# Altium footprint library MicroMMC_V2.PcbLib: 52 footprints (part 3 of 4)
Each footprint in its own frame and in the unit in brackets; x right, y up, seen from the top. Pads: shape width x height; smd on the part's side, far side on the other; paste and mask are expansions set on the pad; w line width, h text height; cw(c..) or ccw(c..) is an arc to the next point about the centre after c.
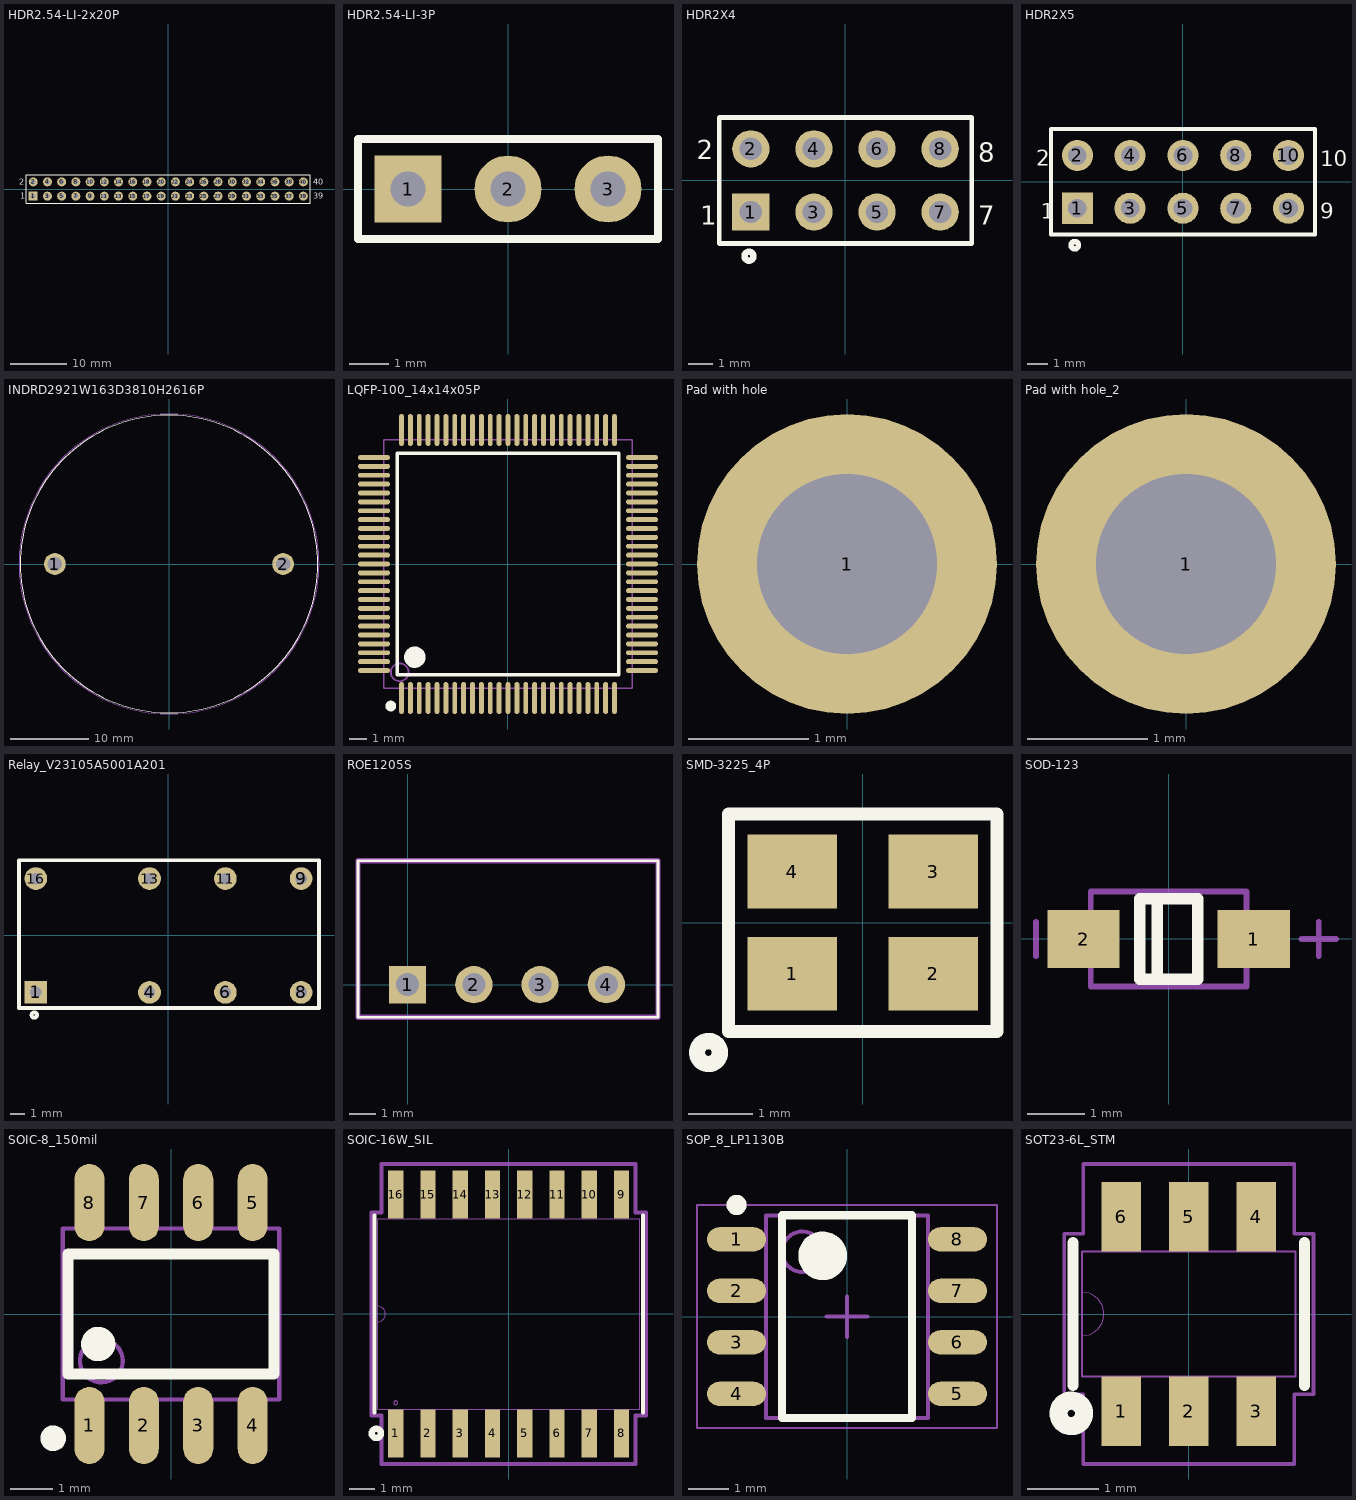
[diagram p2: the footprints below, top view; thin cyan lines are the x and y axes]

## HDR2.54-LI-2x20P [mm] "双排排针，20x2脚"
pads (40):
  rect 1.6x1.6 hole 0.9: 1(-24.13,-1.27)
  round 1.6 hole 0.9: 2(-24.13,1.27) 3(-21.59,-1.27) 4(-21.59,1.27) 5(-19.05,-1.27) 6(-19.05,1.27) 7(-16.51,-1.27) 8(-16.51,1.27) 9(-13.97,-1.27) 10(-13.97,1.27) 11(-11.43,-1.27) 12(-11.43,1.27) 13(-8.89,-1.27) 14(-8.89,1.27) 15(-6.35,-1.27) 16(-6.35,1.27) 17(-3.81,-1.27) 18(-3.81,1.27) 19(-1.27,-1.27) 20(-1.27,1.27) 21(1.27,-1.27) 22(1.27,1.27) 23(3.81,-1.27) 24(3.81,1.27) 25(6.35,-1.27) 26(6.35,1.27) 27(8.89,-1.27) 28(8.89,1.27) 29(11.43,-1.27) 30(11.43,1.27) 31(13.97,-1.27) 32(13.97,1.27) 33(16.51,-1.27) 34(16.51,1.27) 35(19.05,-1.27) 36(19.05,1.27) 37(21.59,-1.27) 38(21.59,1.27) 39(24.13,-1.27) 40(24.13,1.27)
Top Overlay:
  lines w0.2: -25.4,-2.54 25.4,-2.54 25.4,2.54 -25.4,2.54 -25.4,-2.54
  text "1" at -26.416,-1.778 h1.02
  text "2" at -26.67,0.762 h1.02
  text "40" at 25.908,0.762 h1.02
  text "39" at 25.908,-1.778 h1.02
3D body "HDR2.54-1x2P.STEP": height 8.5, standoff -3, extent 17.78,-2.54 20.32,2.54
3D body "HDR2.54-1x2P.STEP": height 8.5, standoff -3, extent 20.32,-2.54 22.86,2.54
3D body "HDR2.54-1x2P.STEP": height 8.5, standoff -3, extent 12.7,-2.54 15.24,2.54
3D body "HDR2.54-1x2P.STEP": height 8.5, standoff -3, extent 15.24,-2.54 17.78,2.54
3D body "HDR2.54-1x2P.STEP": height 8.5, standoff -3, extent 22.86,-2.54 25.4,2.54
3D body "HDR2.54-1x2P.STEP": height 8.5, standoff -3, extent 5.08,-2.54 7.62,2.54
3D body "HDR2.54-1x2P.STEP": height 8.5, standoff -3, extent 7.62,-2.54 10.16,2.54
3D body "HDR2.54-1x2P.STEP": height 8.5, standoff -3, extent 0,-2.54 2.54,2.54
3D body "HDR2.54-1x2P.STEP": height 8.5, standoff -3, extent 2.54,-2.54 5.08,2.54
3D body "HDR2.54-1x2P.STEP": height 8.5, standoff -3, extent 10.16,-2.54 12.7,2.54
3D body "HDR2.54-1x2P.STEP": height 8.5, standoff -3, extent -7.62,-2.54 -5.08,2.54
3D body "HDR2.54-1x2P.STEP": height 8.5, standoff -3, extent -5.08,-2.54 -2.54,2.54
3D body "HDR2.54-1x2P.STEP": height 8.5, standoff -3, extent -12.7,-2.54 -10.16,2.54
3D body "HDR2.54-1x2P.STEP": height 8.5, standoff -3, extent -10.16,-2.54 -7.62,2.54
3D body "HDR2.54-1x2P.STEP": height 8.5, standoff -3, extent -2.54,-2.54 0,2.54
3D body "HDR2.54-1x2P.STEP": height 8.5, standoff -3, extent -20.32,-2.54 -17.78,2.54
3D body "HDR2.54-1x2P.STEP": height 8.5, standoff -3, extent -17.78,-2.54 -15.24,2.54
3D body "HDR2.54-1x2P.STEP": height 8.5, standoff -3, extent -25.4,-2.54 -22.86,2.54
3D body "HDR2.54-1x2P.STEP": height 8.5, standoff -3, extent -22.86,-2.54 -20.32,2.54
3D body "HDR2.54-1x2P.STEP": height 8.5, standoff -3, extent -15.24,-2.54 -12.7,2.54

## HDR2.54-LI-3P [mm] "排针，3脚"
pads (3):
  rect 1.7x1.7 hole 0.9: 1(-2.54,0)
  round 1.7 hole 0.9: 2(0,0) 3(2.54,0)
Top Overlay:
  lines w0.2: -3.81,-1.27 -3.81,1.27 3.81,1.27 3.81,-1.27 -3.81,-1.27
3D body "HDR2.54-1P.STEP": height 8.5, standoff -3, extent 1.27,-1.27 3.81,1.27
3D body "HDR2.54-1P.STEP": height 8.5, standoff -3, extent -1.27,-1.27 1.27,1.27
3D body "HDR2.54-1P.STEP": height 8.5, standoff -3, extent -3.81,-1.27 -1.27,1.27

## HDR2X4 [mm] "Connector; Header; 4x2 Position"
pads (8):
  rect 1.5x1.5 hole 0.9: 1(-3.81,-1.27)
  round 1.5 hole 0.9: 2(-3.81,1.27) 3(-1.27,-1.27) 4(-1.27,1.27) 5(1.27,-1.27) 6(1.27,1.27) 7(3.81,-1.27) 8(3.81,1.27)
Top Overlay:
  circle w0.254: c-3.884,-3.048 r0.18
  lines w0.2: -5.08,-2.54 5.08,-2.54 5.08,2.54 -5.08,2.54 -5.08,-2.54
  text "2" at -5.975,0.852 h0.76
  text "1" at -5.842,-1.778 h0.76
  text "7" at 5.334,-1.778 h0.76
  text "8" at 5.334,0.762 h0.76

## HDR2X5 [mm] "Connector; Header; 5x2 Position"
pads (10):
  rect 1.5x1.5 hole 0.9: 1(-5.08,-1.27)
  round 1.5 hole 0.9: 2(-5.08,1.27) 3(-2.54,-1.27) 4(-2.54,1.27) 5(0,-1.27) 6(0,1.27) 7(2.54,-1.27) 8(2.54,1.27) 9(5.08,-1.27) 10(5.08,1.27)
Top Overlay:
  circle w0.254: c-5.207,-3.048 r0.18
  lines w0.2: -6.35,-2.54 6.35,-2.54 6.35,2.54 -6.35,2.54 -6.35,-2.54
  text "2" at -7.071,0.787 h0.76
  text "1" at -6.853,-1.77 h0.76
  text "9" at 6.604,-1.778 h0.76
  text "10" at 6.604,0.762 h0.76

## INDRD2921W163D3810H2616P [mm]
pads (2):
  round 2.8 hole 1.85: 1(-14.605,0) 2(14.605,0)
Top Overlay:
  circle w0.127: c0,0 r19.05
Mechanical 15:
  circle w0.127: c0,0 r19.2
3D body "1140-122k-rc.stp": height 26.23, standoff -12.63, extent -19.05,-19.05 19.05,19.05

## LQFP-100_14x14x05P [mm]
pads (100):
  oval 0.28x1.8 smd: 1(-6,-7.55) 2(-5.5,-7.55) 3(-5,-7.55) 4(-4.5,-7.55) 5(-4,-7.55) 6(-3.5,-7.55) 7(-3,-7.55) 8(-2.5,-7.55) 9(-2,-7.55) 10(-1.5,-7.55) 11(-1,-7.55) 12(-0.5,-7.55) 13(0,-7.55) 14(0.5,-7.55) 15(1,-7.55) 16(1.5,-7.55) 17(2,-7.55) 18(2.5,-7.55) 19(3,-7.55) 20(3.5,-7.55) 21(4,-7.55) 22(4.5,-7.55) 23(5,-7.55) 24(5.5,-7.55) 25(6,-7.55) 51(6,7.55) 52(5.5,7.55) 53(5,7.55) 54(4.5,7.55) 55(4,7.55) 56(3.5,7.55) 57(3,7.55) 58(2.5,7.55) 59(2,7.55) 60(1.5,7.55) 61(1,7.55) 62(0.5,7.55) 63(0,7.55) 64(-0.5,7.55) 65(-1,7.55) 66(-1.5,7.55) 67(-2,7.55) 68(-2.5,7.55) 69(-3,7.55) 70(-3.5,7.55) 71(-4,7.55) 72(-4.5,7.55) 73(-5,7.55) 74(-5.5,7.55) 75(-6,7.55)
  oval 1.8x0.28 smd: 26(7.55,-6) 27(7.55,-5.5) 28(7.55,-5) 29(7.55,-4.5) 30(7.55,-4) 31(7.55,-3.5) 32(7.55,-3) 33(7.55,-2.5) 34(7.55,-2) 35(7.55,-1.5) 36(7.55,-1) 37(7.55,-0.5) 38(7.55,0) 39(7.55,0.5) 40(7.55,1) 41(7.55,1.5) 42(7.55,2) 43(7.55,2.5) 44(7.55,3) 45(7.55,3.5) 46(7.55,4) 47(7.55,4.5) 48(7.55,5) 49(7.55,5.5) 50(7.55,6) 76(-7.55,6) 77(-7.55,5.5) 78(-7.55,5) 79(-7.55,4.5) 80(-7.55,4) 81(-7.55,3.5) 82(-7.55,3) 83(-7.55,2.5) 84(-7.55,2) 85(-7.55,1.5) 86(-7.55,1) 87(-7.55,0.5) 88(-7.55,0) 89(-7.55,-0.5) 90(-7.55,-1) 91(-7.55,-1.5) 92(-7.55,-2) 93(-7.55,-2.5) 94(-7.55,-3) 95(-7.55,-3.5) 96(-7.55,-4) 97(-7.55,-4.5) 98(-7.55,-5) 99(-7.55,-5.5) 100(-7.55,-6)
Top Overlay:
  circle w0.6: c-5.25,-5.25 r0.3
  circle w0.3: c-6.604,-8.001 r0.15
  lines w0.2: -6.25,-6.25 6.25,-6.25 6.25,6.25 -6.25,6.25 -6.25,-6.25
Mechanical 13:
  circle w0.1: c-6.1,-6.1 r0.5
  lines w0.1: -7,-7 7,-7 7,7 -7,7 -7,-7
3D body "LQFP-100.STEP": height 1.6, standoff 0, extent -8,-8 8,8

## Pad with hole [mm]
pads (1):
  round 2.5 hole 1.5: 1(0,0)

## Pad with hole_2 [mm]
pads (1):
  round 2.5 hole 1.5: 1(0,0)

## Relay_V23105A5001A201 [mil] "V23105A5001A201"
pads (8):
  rect 60x60 hole 30: 1(-350,-150)
  round 60 hole 30: 4(-50,-150) 6(150,-150) 8(350,-150) 9(350,150) 11(150,150) 13(-50,150) 16(-350,150)
Top Overlay:
  circle w10: c-354.02,-210 r7.07
  lines w10: -394.29,-191.34 397.05,-191.34 397.05,198.43 -394.29,198.43 -394.29,-191.34
3D body "V23105A5001A201_Relay v2.step": height 425.7, standoff -78.24, extent -394.29,-191.34 397.05,198.42

## ROE1205S [mm]
pads (4):
  rect 1.43x1.43 hole 0.88: 1(0,0)
  round 1.43 hole 0.88: 2(2.54,0) 3(5.08,0) 4(7.62,0)
Top Overlay:
  lines w0.1: -1.9,-1.25 9.6,-1.25 9.6,4.75 -1.9,4.75 -1.9,-1.25
Mechanical 13:
  lines w0.2: -1.9,-1.25 9.6,-1.25 9.6,4.75 -1.9,4.75 -1.9,-1.25
3D body "ROE-0512S.stp": height 10.6, standoff -5, extent -1.9,-1.25 9.6,4.75

## SMD-3225_4P [mm]
pads (4):
  rect 1.4x1.15 smd: 1(-1.1,-0.8) 2(1.1,-0.8) 3(1.1,0.8) 4(-1.1,0.8)
Top Overlay:
  circle w0.254: c-2.413,-2.032 r0.18
  lines w0.203: -2.1,-1.7 2.1,-1.7 2.1,1.7 -2.1,1.7 -2.1,-1.7
3D body "User Library-3225-1.STEP": height 0.61, standoff 0, extent -1.6,-1.25 1.6,1.25

## SOD-123 [mm]
pads (2):
  rect 1.25x1 smd: 1(1.475,0) 2(-1.475,0)
Top Overlay:
  lines w0.2: -0.2,-0.7 -0.2,0.7 ; -0.5,-0.7 0.5,-0.7 0.5,0.7 -0.5,0.7 -0.5,-0.7
Mechanical 13:
  lines w0.1: -1.35,-0.825 -1.35,0.825 1.35,0.825 1.35,-0.825 -1.35,-0.825
Mechanical 15:
  lines w0.1: -2.3,-0.3 -2.3,0.3 ; 2.3,0 2.9,0 ; 2.6,-0.3 2.6,0.3
3D body "SOD123.STEP": height 1.35, standoff 0, extent -1.85,-0.775 1.85,0.775

## SOIC-8_150mil [mm]
pads (8):
  oval 0.7x1.8 smd: 1(-1.905,-2.6) 2(-0.635,-2.6) 3(0.635,-2.6) 4(1.905,-2.6) 5(1.905,2.6) 6(0.635,2.6) 7(-0.635,2.6) 8(-1.905,2.6)
Top Overlay:
  circle w0.4: c-1.7,-0.7 r0.2
  circle w0.3: c-2.75,-2.9 r0.15
  lines w0.254: -2.4,-1.4 -2.4,1.4 2.4,1.4 2.4,-1.4 -2.4,-1.4
Mechanical 13:
  circle w0.1: c-1.625,-1.095 r0.5
  lines w0.1: -2.525,-1.995 -2.525,1.995 2.525,1.995 2.525,-1.995 -2.525,-1.995

## SOIC-16W_SIL [mm] "SI8641BD-B-ISR"
pads (16):
  rect 0.6x1.9 smd: 1(-4.445,-4.7) 2(-3.175,-4.7) 3(-1.905,-4.7) 4(-0.635,-4.7) 5(0.635,-4.7) 6(1.905,-4.7) 7(3.175,-4.7) 8(4.445,-4.7) 9(4.445,4.7) 10(3.175,4.7) 11(1.905,4.7) 12(0.635,4.7) 13(-0.635,4.7) 14(-1.905,4.7) 15(-3.175,4.7) 16(-4.445,4.7)
Top Overlay:
  circle w0.254: c-5.207,-4.699 r0.18
  lines w0.152: -5.283,-3.873 -5.283,3.874 ; 5.283,-3.873 5.283,3.874
Mechanical 13:
  circle w0: c-4.445,-3.492 r0.076
  lines w0: -5.156,-0.305 ccw(c-5.156,0) -5.156,0.305
  lines w0.025: -5.156,-3.746 5.156,-3.746 5.156,3.747 -5.156,3.747 -5.156,-3.746
Mechanical 15:
  lines w0.152: -5.41,-4 -5.41,4.001 -4.999,4.001 -4.999,5.904 4.999,5.904 4.999,4.001 5.41,4.001 5.41,-4 4.999,-4 4.999,-5.904 -4.999,-5.904 -4.999,-4 -5.41,-4
3D body: height 0.25, standoff 0, extent -0.254,0 0,0.254
3D body "SOIC-16W_SIL.step": height 2.64, standoff 0, extent -5.156,-5.3 5.156,5.3

## SOP_8_LP1130B [mm]
height 1.75
pads (8):
  oval 1.45x0.6 smd: 1(-2.725,1.905) 2(-2.725,0.635) 3(-2.725,-0.635) 4(-2.725,-1.905) 5(2.725,-1.905) 6(2.725,-0.635) 7(2.725,0.635) 8(2.725,1.905)
Top Overlay:
  circle w0.6: c-0.6,1.5 r0.3
  circle w0.25: c-2.725,2.755 r0.125
  lines w0.2: -1.6,-2.5 1.6,-2.5 1.6,2.5 -1.6,2.5 -1.6,-2.5
Mechanical 13:
  circle w0.1: c-1.1,1.6 r0.5
  lines w0.1: -2,-2.5 2,-2.5 2,2.5 -2,2.5 -2,-2.5
Mechanical 15:
  lines w0.05: -3.7,-2.75 3.7,-2.75 3.7,2.75 -3.7,2.75 -3.7,-2.75
  lines w0.1: -0.5,0 0.5,0 ; 0,-0.5 0,0.5
3D body "SOP_8_LP1130B.step": height 1.75, standoff 0, extent -3,-2.5 3,2.5

## SOT23-6L_STM [mil] "USBLC62SC6"
pads (6):
  rect 22x38.5 smd paste+0 mask+0: 1(-37.4,-53.75) 2(0,-53.75) 3(37.4,-53.75) 4(37.4,53.75) 5(0,53.75) 6(-37.4,53.75)
Top Overlay:
  circle w10: c-65,-55 r7.07
  lines w6: -64,-39.5 -64,39.5 ; 64,-39.5 64,39.5
Mechanical 13:
  lines w0: -59,-12 ccw(c-59,0) -59,12
  lines w1: -59,-34.5 59,-34.5 59,34.5 -59,34.5 -59,-34.5 ; -47.4,-59 -27.4,-59 -27.4,-34.5 -47.4,-34.5 -47.4,-59 ; -47.4,34.5 -47.4,59 -27.4,59 -27.4,34.5 -47.4,34.5 ; -10,-59 10,-59 10,-34.5 -10,-34.5 -10,-59 ; -10,34.5 -10,59 10,59 10,34.5 -10,34.5 ; 27.4,-59 47.4,-59 47.4,-34.5 27.4,-34.5 27.4,-59 ; 27.4,34.5 27.4,59 47.4,59 47.4,34.5 27.4,34.5
Mechanical 15:
  lines w1.97: -69,-44.5 -58.4,-44.5 -58.4,-83 58.4,-83 58.4,-44.5 69,-44.5 69,44.5 58.4,44.5 58.4,83 -58.4,83 -58.4,44.5 -69,44.5 -69,-44.5
3D body: height 10, standoff 0, extent -10,0 0,10
3D body "SOT23-6L_STM.step": height 57.09, standoff 0, extent -59.02,-64.01 59.01,54.02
